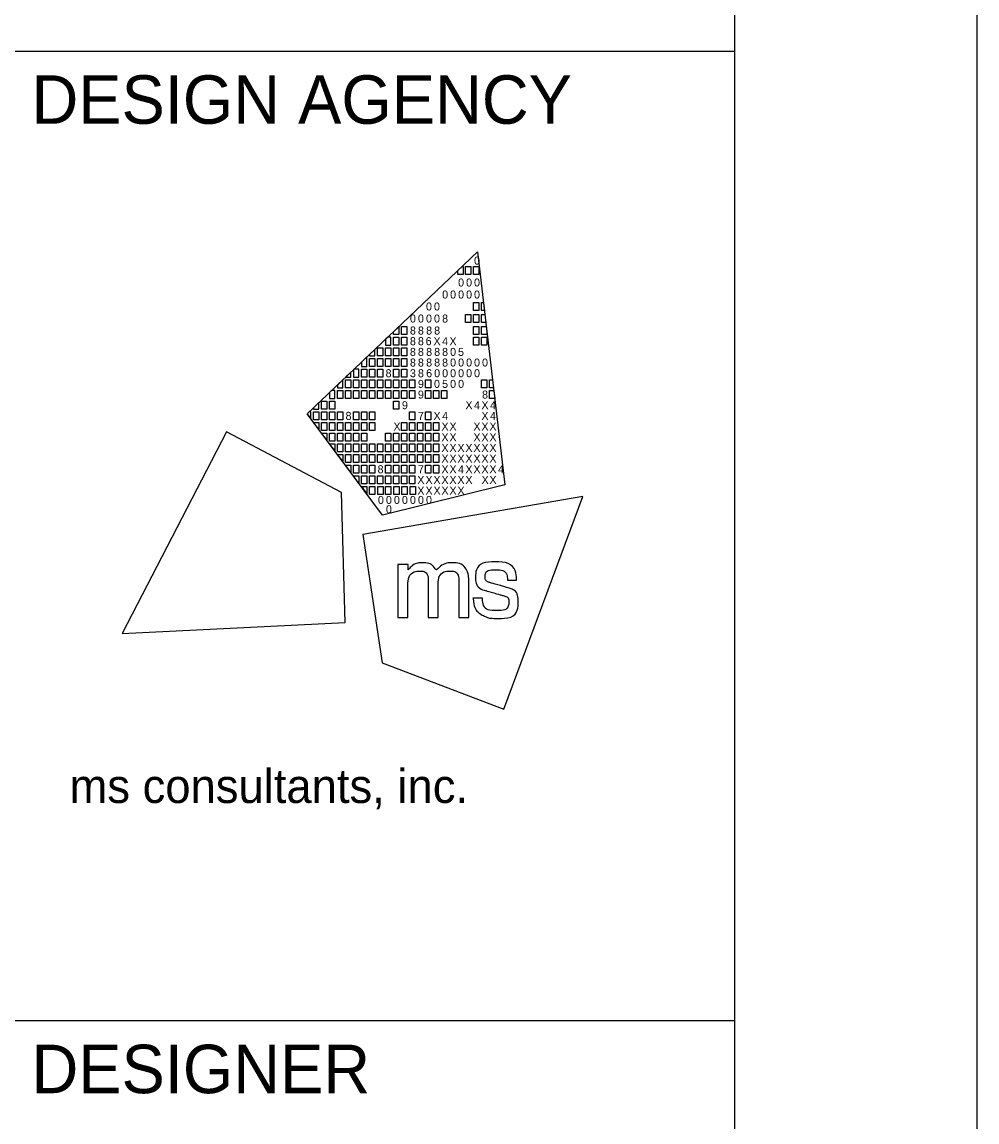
# Model space of a CAD drawing. Extents: x 0.1 to 34.1, y 0.2 to 22.2.
# Drawn here: x 32.139 to 34.108, y 2.456 to 4.725 of the extents above; entities that cross this region are included whole.
import ezdxf

# ---------------------------------------------------------------- set-up
doc = ezdxf.new("R2010")
doc.units = 0
for name, color, linetype in [('Default', 7, 'Continuous'), ('SH_Border', 7, 'Continuous'), ('SH_Cut_Line', 7, 'Continuous'), ('SH_Data', 7, 'Continuous')]:
    doc.layers.add(name, color=color, linetype=linetype)

msp = doc.modelspace()

# ---------------------------------------------------------------- linework, layer by layer
at = {"layer": 'Default'}
for p, q in [((32.7267, 3.9169), (33.0779, 4.2511)), ((33.0779, 4.2511), (33.0779, 4.2511)), ((33.0779, 4.2511), (33.1344, 3.7702)), ((32.8821, 3.708), (32.7267, 3.9169)), ((33.1344, 3.7702), (32.8821, 3.708))]:
    msp.add_line(p, q, dxfattribs=at)
for points in [[(33.0371, 4.2122), (33.046, 4.2208), (33.0481, 4.2208), (33.0481, 4.2043), (33.0371, 4.2043)], [(33.0535, 4.2208), (33.0645, 4.2208), (33.0645, 4.2043), (33.0535, 4.2043)], [(33.07, 4.2208), (33.081, 4.2208), (33.081, 4.2043), (33.07, 4.2043)], [(33.0697, 4.1465), (33.0807, 4.1465), (33.0807, 4.13), (33.0697, 4.13)], [(33.0862, 4.1465), (33.0902, 4.1465), (33.0921, 4.13), (33.0862, 4.13)], [(33.0533, 4.1217), (33.0643, 4.1217), (33.0643, 4.1052), (33.0533, 4.1052)], [(33.0697, 4.1217), (33.0807, 4.1217), (33.0807, 4.1052), (33.0697, 4.1052)], [(33.0862, 4.1217), (33.0931, 4.1217), (33.0951, 4.1052), (33.0862, 4.1052)], [(32.9045, 4.0861), (32.9155, 4.0966), (32.9155, 4.0804), (32.9045, 4.0804)], [(32.9214, 4.0969), (32.9324, 4.0969), (32.9324, 4.0804), (32.9214, 4.0804)], [(33.0697, 4.0969), (33.0807, 4.0969), (33.0807, 4.0804), (33.0697, 4.0804)], [(33.0862, 4.0969), (33.096, 4.0969), (33.0972, 4.0868), (33.0972, 4.0804), (33.0862, 4.0804)], [(32.9049, 4.0749), (32.9159, 4.0749), (32.9159, 4.0584), (32.9049, 4.0584)], [(32.9214, 4.0749), (32.9324, 4.0749), (32.9324, 4.0584), (32.9214, 4.0584)], [(33.0697, 4.0749), (33.0807, 4.0749), (33.0807, 4.0584), (33.0697, 4.0584)], [(33.0862, 4.0749), (33.0972, 4.0749), (33.0972, 4.0584), (33.0862, 4.0584)], [(32.8719, 4.0529), (32.8829, 4.0529), (32.8829, 4.0364), (32.8719, 4.0364)], [(32.8884, 4.0529), (32.8994, 4.0529), (32.8994, 4.0364), (32.8884, 4.0364)], [(32.9049, 4.0529), (32.9159, 4.0529), (32.9159, 4.0364), (32.9049, 4.0364)], [(32.9214, 4.0529), (32.9324, 4.0529), (32.9324, 4.0364), (32.9214, 4.0364)], [(32.8554, 4.0309), (32.8664, 4.0309), (32.8664, 4.0144), (32.8554, 4.0144)], [(32.8719, 4.0309), (32.8829, 4.0309), (32.8829, 4.0144), (32.8719, 4.0144)], [(32.8884, 4.0309), (32.8994, 4.0309), (32.8994, 4.0144), (32.8884, 4.0144)], [(32.9049, 4.0309), (32.9159, 4.0309), (32.9159, 4.0144), (32.9049, 4.0144)], [(32.9214, 4.0309), (32.9324, 4.0309), (32.9324, 4.0144), (32.9214, 4.0144)], [(32.8388, 4.0089), (32.8499, 4.0089), (32.8499, 3.9923), (32.8388, 3.9923)], [(32.8554, 4.0089), (32.8664, 4.0089), (32.8664, 3.9923), (32.8554, 3.9923)], [(32.8719, 4.0089), (32.8829, 4.0089), (32.8829, 3.9923), (32.8719, 3.9923)], [(32.9049, 4.0089), (32.9159, 4.0089), (32.9159, 3.9923), (32.9049, 3.9923)], [(32.9214, 4.0089), (32.9324, 4.0089), (32.9324, 3.9923), (32.9214, 3.9923)], [(32.8058, 3.9868), (32.8168, 3.9868), (32.8168, 3.9703), (32.8058, 3.9703)], [(32.8223, 3.9868), (32.8333, 3.9868), (32.8333, 3.9703), (32.8223, 3.9703)], [(32.8388, 3.9868), (32.8499, 3.9868), (32.8499, 3.9703), (32.8388, 3.9703)], [(32.8554, 3.9868), (32.8664, 3.9868), (32.8664, 3.9703), (32.8554, 3.9703)], [(32.8719, 3.9868), (32.8829, 3.9868), (32.8829, 3.9703), (32.8719, 3.9703)], [(32.8884, 3.9868), (32.8994, 3.9868), (32.8994, 3.9703), (32.8884, 3.9703)], [(32.9049, 3.9868), (32.9159, 3.9868), (32.9159, 3.9703), (32.9049, 3.9703)], [(32.9214, 3.9868), (32.9324, 3.9868), (32.9324, 3.9703), (32.9214, 3.9703)], [(32.9379, 3.9868), (32.9489, 3.9868), (32.9489, 3.9703), (32.9379, 3.9703)], [(32.971, 3.9868), (32.982, 3.9868), (32.982, 3.9703), (32.971, 3.9703)], [(33.0862, 3.9868), (33.0972, 3.9868), (33.0972, 3.9703), (33.0862, 3.9703)], [(33.1027, 3.9868), (33.109, 3.9868), (33.1109, 3.9703), (33.1027, 3.9703)], [(32.7893, 3.9648), (32.8003, 3.9648), (32.8003, 3.9483), (32.7893, 3.9483)], [(32.8058, 3.9648), (32.8168, 3.9648), (32.8168, 3.9483), (32.8058, 3.9483)], [(32.8223, 3.9648), (32.8333, 3.9648), (32.8333, 3.9483), (32.8223, 3.9483)], [(32.8388, 3.9648), (32.8499, 3.9648), (32.8499, 3.9483), (32.8388, 3.9483)], [(32.8554, 3.9648), (32.8664, 3.9648), (32.8664, 3.9483), (32.8554, 3.9483)], [(32.8719, 3.9648), (32.8829, 3.9648), (32.8829, 3.9483), (32.8719, 3.9483)], [(32.8884, 3.9648), (32.8994, 3.9648), (32.8994, 3.9483), (32.8884, 3.9483)], [(32.9049, 3.9648), (32.9159, 3.9648), (32.9159, 3.9483), (32.9049, 3.9483)], [(32.9214, 3.9648), (32.9324, 3.9648), (32.9324, 3.9483), (32.9214, 3.9483)], [(32.9379, 3.9648), (32.9489, 3.9648), (32.9489, 3.9483), (32.9379, 3.9483)], [(32.971, 3.9648), (32.982, 3.9648), (32.982, 3.9483), (32.971, 3.9483)], [(32.9875, 3.9648), (32.9985, 3.9648), (32.9985, 3.9483), (32.9875, 3.9483)], [(33.0038, 3.9648), (33.0149, 3.9648), (33.0149, 3.9483), (33.0038, 3.9483)], [(33.1027, 3.9648), (33.1116, 3.9648), (33.1135, 3.9483), (33.1027, 3.9483)], [(32.7563, 3.9428), (32.7673, 3.9428), (32.7673, 3.9263), (32.7563, 3.9263)], [(32.7728, 3.9428), (32.7838, 3.9428), (32.7838, 3.9263), (32.7728, 3.9263)], [(32.9049, 3.9428), (32.9159, 3.9428), (32.9159, 3.9263), (32.9049, 3.9263)], [(32.7398, 3.9208), (32.7508, 3.9208), (32.7508, 3.9043), (32.7398, 3.9043)], [(32.7563, 3.9208), (32.7673, 3.9208), (32.7673, 3.9043), (32.7563, 3.9043)], [(32.7728, 3.9208), (32.7838, 3.9208), (32.7838, 3.9043), (32.7728, 3.9043)], [(32.7893, 3.9208), (32.8003, 3.9208), (32.8003, 3.9043), (32.7893, 3.9043)], [(32.8223, 3.9208), (32.8333, 3.9208), (32.8333, 3.9043), (32.8223, 3.9043)], [(32.8388, 3.9208), (32.8499, 3.9208), (32.8499, 3.9043), (32.8388, 3.9043)], [(32.8554, 3.9208), (32.8664, 3.9208), (32.8664, 3.9043), (32.8554, 3.9043)], [(32.9379, 3.9208), (32.9489, 3.9208), (32.9489, 3.9043), (32.9379, 3.9043)], [(32.971, 3.9208), (32.982, 3.9208), (32.982, 3.9043), (32.971, 3.9043)], [(32.7398, 3.8988), (32.7508, 3.8988), (32.7508, 3.885)], [(32.7563, 3.8988), (32.7673, 3.8988), (32.7673, 3.8823), (32.7563, 3.8823)], [(32.7728, 3.8988), (32.7838, 3.8988), (32.7838, 3.8823), (32.7728, 3.8823)], [(32.7893, 3.8988), (32.8003, 3.8988), (32.8003, 3.8823), (32.7893, 3.8823)], [(32.8058, 3.8988), (32.8168, 3.8988), (32.8168, 3.8823), (32.8058, 3.8823)], [(32.8223, 3.8988), (32.8333, 3.8988), (32.8333, 3.8823), (32.8223, 3.8823)], [(32.8388, 3.8988), (32.8499, 3.8988), (32.8499, 3.8823), (32.8388, 3.8823)], [(32.8554, 3.8988), (32.8664, 3.8988), (32.8664, 3.8823), (32.8554, 3.8823)], [(32.9214, 3.8988), (32.9324, 3.8988), (32.9324, 3.8823), (32.9214, 3.8823)], [(32.9379, 3.8988), (32.9489, 3.8988), (32.9489, 3.8823), (32.9379, 3.8823)], [(32.9544, 3.8988), (32.9655, 3.8988), (32.9655, 3.8823), (32.9544, 3.8823)], [(32.971, 3.8988), (32.982, 3.8988), (32.982, 3.8823), (32.971, 3.8823)], [(32.9875, 3.8988), (32.9985, 3.8988), (32.9985, 3.8823), (32.9875, 3.8823)], [(32.7563, 3.8767), (32.7673, 3.8767), (32.7673, 3.863)], [(32.7728, 3.8767), (32.7838, 3.8767), (32.7838, 3.8602), (32.7728, 3.8602)], [(32.7893, 3.8767), (32.8003, 3.8767), (32.8003, 3.8602), (32.7893, 3.8602)], [(32.8058, 3.8767), (32.8168, 3.8767), (32.8168, 3.8602), (32.8058, 3.8602)], [(32.8223, 3.8767), (32.8333, 3.8767), (32.8333, 3.8602), (32.8223, 3.8602)], [(32.8388, 3.8767), (32.8499, 3.8767), (32.8499, 3.8602), (32.8388, 3.8602)], [(32.8884, 3.8767), (32.8994, 3.8767), (32.8994, 3.8602), (32.8884, 3.8602)], [(32.9049, 3.8767), (32.9159, 3.8767), (32.9159, 3.8602), (32.9049, 3.8602)], [(32.9214, 3.8767), (32.9324, 3.8767), (32.9324, 3.8602), (32.9214, 3.8602)], [(32.9379, 3.8767), (32.9489, 3.8767), (32.9489, 3.8602), (32.9379, 3.8602)], [(32.9544, 3.8767), (32.9655, 3.8767), (32.9655, 3.8602), (32.9544, 3.8602)], [(32.971, 3.8767), (32.982, 3.8767), (32.982, 3.8602), (32.971, 3.8602)], [(32.9875, 3.8767), (32.9985, 3.8767), (32.9985, 3.8602), (32.9875, 3.8602)], [(32.7728, 3.8547), (32.7838, 3.8547), (32.7838, 3.841)], [(32.7838, 3.8547), (32.7838, 3.8547), (32.7838, 3.8547)], [(32.7893, 3.8547), (32.8003, 3.8547), (32.8003, 3.8382), (32.7893, 3.8382)], [(32.8058, 3.8547), (32.8168, 3.8547), (32.8168, 3.8382), (32.8058, 3.8382)], [(32.8223, 3.8547), (32.8333, 3.8547), (32.8333, 3.8382), (32.8223, 3.8382)], [(32.8388, 3.8547), (32.8499, 3.8547), (32.8499, 3.8382), (32.8388, 3.8382)], [(32.8554, 3.8547), (32.8664, 3.8547), (32.8664, 3.8382), (32.8554, 3.8382)], [(32.8719, 3.8547), (32.8829, 3.8547), (32.8829, 3.8382), (32.8719, 3.8382)], [(32.8884, 3.8547), (32.8994, 3.8547), (32.8994, 3.8382), (32.8884, 3.8382)], [(32.9049, 3.8547), (32.9159, 3.8547), (32.9159, 3.8382), (32.9049, 3.8382)], [(32.9214, 3.8547), (32.9324, 3.8547), (32.9324, 3.8382), (32.9214, 3.8382)], [(32.9379, 3.8547), (32.9489, 3.8547), (32.9489, 3.8382), (32.9379, 3.8382)], [(32.9544, 3.8547), (32.9655, 3.8547), (32.9655, 3.8382), (32.9544, 3.8382)], [(32.971, 3.8547), (32.982, 3.8547), (32.982, 3.8382), (32.971, 3.8382)], [(32.9875, 3.8547), (32.9985, 3.8547), (32.9985, 3.8382), (32.9875, 3.8382)], [(32.7893, 3.8327), (32.8003, 3.8327), (32.8003, 3.8189)], [(32.8058, 3.8327), (32.8168, 3.8327), (32.8168, 3.8162), (32.8058, 3.8162)], [(32.8223, 3.8327), (32.8333, 3.8327), (32.8333, 3.8162), (32.8223, 3.8162)], [(32.8388, 3.8327), (32.8499, 3.8327), (32.8499, 3.8162), (32.8388, 3.8162)], [(32.8554, 3.8327), (32.8664, 3.8327), (32.8664, 3.8162), (32.8554, 3.8162)], [(32.8719, 3.8327), (32.8829, 3.8327), (32.8829, 3.8162), (32.8719, 3.8162)], [(32.8884, 3.8327), (32.8994, 3.8327), (32.8994, 3.8162), (32.8884, 3.8162)], [(32.9049, 3.8327), (32.9159, 3.8327), (32.9159, 3.8162), (32.9049, 3.8162)], [(32.9214, 3.8327), (32.9324, 3.8327), (32.9324, 3.8162), (32.9214, 3.8162)], [(32.9379, 3.8327), (32.9489, 3.8327), (32.9489, 3.8162), (32.9379, 3.8162)], [(32.9544, 3.8327), (32.9655, 3.8327), (32.9655, 3.8162), (32.9544, 3.8162)], [(32.971, 3.8327), (32.982, 3.8327), (32.982, 3.8162), (32.971, 3.8162)], [(32.9875, 3.8327), (32.9985, 3.8327), (32.9985, 3.8162), (32.9875, 3.8162)], [(32.8169, 3.7955), (32.8057, 3.8107), (32.8169, 3.8107)], [(32.8223, 3.8107), (32.8333, 3.8107), (32.8333, 3.7942), (32.8223, 3.7942)], [(32.8388, 3.8107), (32.8499, 3.8107), (32.8499, 3.7942), (32.8388, 3.7942)], [(32.8554, 3.8107), (32.8664, 3.8107), (32.8664, 3.7942), (32.8554, 3.7942)], [(32.8884, 3.8107), (32.8994, 3.8107), (32.8994, 3.7942), (32.8884, 3.7942)], [(32.9049, 3.8107), (32.9159, 3.8107), (32.9159, 3.7942), (32.9049, 3.7942)], [(32.9214, 3.8107), (32.9324, 3.8107), (32.9324, 3.7942), (32.9214, 3.7942)], [(32.9379, 3.8107), (32.9489, 3.8107), (32.9489, 3.7942), (32.9379, 3.7942)], [(32.971, 3.8107), (32.982, 3.8107), (32.982, 3.7942), (32.971, 3.7942)], [(32.9875, 3.8107), (32.9985, 3.8107), (32.9985, 3.7942), (32.9875, 3.7942)], [(32.8331, 3.7732), (32.8223, 3.7887), (32.8333, 3.7887)], [(32.8388, 3.7887), (32.8499, 3.7887), (32.8499, 3.7722), (32.8388, 3.7722)], [(32.8554, 3.7887), (32.8664, 3.7887), (32.8664, 3.7722), (32.8554, 3.7722)], [(32.8719, 3.7887), (32.8829, 3.7887), (32.8829, 3.7722), (32.8719, 3.7722)], [(32.8884, 3.7887), (32.8994, 3.7887), (32.8994, 3.7722), (32.8884, 3.7722)], [(32.9049, 3.7887), (32.9159, 3.7887), (32.9159, 3.7722), (32.9049, 3.7722)], [(32.9214, 3.7887), (32.9324, 3.7887), (32.9324, 3.7722), (32.9214, 3.7722)], [(32.9379, 3.7887), (32.9489, 3.7887), (32.9489, 3.7722), (32.9379, 3.7722)], [(32.8393, 3.7667), (32.8499, 3.7667), (32.8499, 3.7525)], [(32.8554, 3.7667), (32.8664, 3.7667), (32.8664, 3.7502), (32.8554, 3.7502)], [(32.8721, 3.7667), (32.8831, 3.7667), (32.8831, 3.7502), (32.8721, 3.7502)], [(32.8885, 3.7667), (32.8995, 3.7667), (32.8995, 3.7502), (32.8885, 3.7502)], [(32.9052, 3.7667), (32.9162, 3.7667), (32.9162, 3.7502), (32.9052, 3.7502)], [(32.9221, 3.7667), (32.9331, 3.7667), (32.9331, 3.7501), (32.9221, 3.7501)], [(32.9388, 3.7667), (32.9498, 3.7667), (32.9498, 3.7501), (32.9388, 3.7501)]]:
    msp.add_lwpolyline(points, close=True, dxfattribs=at)
for points in [[(32.8994, 4.0749), (32.8927, 4.0749), (32.8884, 4.0708), (32.8884, 4.0584), (32.8994, 4.0584), (32.8994, 4.0749)], [(32.8664, 4.0498), (32.8554, 4.0394), (32.8554, 4.0364), (32.8664, 4.0364), (32.8664, 4.0498)], [(32.8499, 4.0341), (32.8388, 4.0237), (32.8388, 4.0144), (32.8499, 4.0144), (32.8499, 4.0341)], [(32.8168, 4.0027), (32.8059, 3.9923), (32.8168, 3.9923), (32.8168, 4.0027)], [(32.8333, 4.0089), (32.8233, 4.0089), (32.8223, 4.008), (32.8223, 3.9923), (32.8333, 3.9923), (32.8333, 4.0089)], [(32.8003, 3.987), (32.7893, 3.9765), (32.7893, 3.9703), (32.8003, 3.9703), (32.8003, 3.987)], [(32.7838, 3.9648), (32.777, 3.9648), (32.7728, 3.9608), (32.7728, 3.9483), (32.7838, 3.9483), (32.7838, 3.9648)], [(32.7508, 3.9399), (32.7398, 3.9294), (32.7398, 3.9263), (32.7508, 3.9263), (32.7508, 3.9399)], [(32.7343, 3.9208), (32.7307, 3.9208), (32.7267, 3.9169), (32.7343, 3.9067), (32.7343, 3.9208)], [(32.5603, 3.8799), (32.345, 3.4638), (32.8048, 3.4865), (32.7975, 3.7542), (32.5603, 3.8799)], [(33.132, 3.3072), (33.295, 3.7464), (32.8415, 3.6679), (32.8813, 3.4031), (33.132, 3.3072)]]:
    msp.add_lwpolyline(points, dxfattribs=at)
for points in [[(32.9139, 3.4965), (32.9139, 3.4965), (32.9139, 3.6059), (32.9139, 3.6059), (32.9139, 3.6059), (32.9346, 3.6059), (32.9346, 3.6059), (32.9346, 3.6059), (32.9346, 3.5947), (32.9346, 3.5947), (32.9437, 3.6049), (32.9548, 3.6095), (32.9647, 3.6095), (32.978, 3.6095), (32.9883, 3.6022), (32.9928, 3.5916), (33.0006, 3.6031), (33.0142, 3.6096), (33.0257, 3.6096), (33.0417, 3.6096), (33.0542, 3.6), (33.0585, 3.5863), (33.0585, 3.5862), (33.0585, 3.5862), (33.0586, 3.5862), (33.0592, 3.584), (33.0598, 3.5822), (33.0598, 3.5721), (33.0598, 3.5721), (33.0598, 3.4964), (33.0598, 3.4964), (33.0598, 3.4964), (33.0394, 3.4964), (33.0394, 3.4964), (33.0394, 3.4964), (33.0394, 3.5698), (33.0394, 3.5698), (33.0394, 3.5851), (33.031, 3.5924), (33.0202, 3.5924), (33.0086, 3.5924), (32.9971, 3.5821), (32.9971, 3.5651), (32.9971, 3.5651), (32.9971, 3.4965), (32.9971, 3.4965), (32.9971, 3.4965), (32.9765, 3.4965), (32.9765, 3.4965), (32.9765, 3.4965), (32.9765, 3.5709), (32.9765, 3.5709), (32.9765, 3.5853), (32.9679, 3.5924), (32.9588, 3.5924), (32.9475, 3.5924), (32.9345, 3.582), (32.9345, 3.5612), (32.9345, 3.5612), (32.9345, 3.4965), (32.9345, 3.4965), (32.9345, 3.4965), (32.9139, 3.4965), (32.9139, 3.4965)], [(33.0687, 3.5359), (33.0687, 3.5359), (33.0686, 3.5367), (33.0686, 3.5367), (33.0686, 3.5367), (33.0695, 3.5367), (33.0695, 3.5367), (33.0695, 3.5367), (33.0874, 3.5367), (33.0874, 3.5367), (33.0874, 3.5367), (33.0881, 3.5367), (33.0881, 3.5367), (33.0881, 3.5367), (33.0881, 3.536), (33.0881, 3.536), (33.0894, 3.5204), (33.0978, 3.511), (33.1181, 3.511), (33.1364, 3.511), (33.1424, 3.5204), (33.1424, 3.5281), (33.1424, 3.5382), (33.1347, 3.5408), (33.1266, 3.543), (33.1266, 3.543), (33.0961, 3.5517), (33.0961, 3.5517), (33.0812, 3.5559), (33.0739, 3.5669), (33.0739, 3.5792), (33.0739, 3.5953), (33.0859, 3.6112), (33.1143, 3.6112), (33.1439, 3.6112), (33.1581, 3.5935), (33.1581, 3.5745), (33.1581, 3.5745), (33.1581, 3.5737), (33.1581, 3.5737), (33.1581, 3.5737), (33.1573, 3.5737), (33.1573, 3.5737), (33.1573, 3.5737), (33.1403, 3.5737), (33.1403, 3.5737), (33.1403, 3.5737), (33.1397, 3.5737), (33.1397, 3.5737), (33.1397, 3.5737), (33.1396, 3.5744), (33.1396, 3.5744), (33.1393, 3.5858), (33.1318, 3.595), (33.1147, 3.595), (33.0982, 3.595), (33.0934, 3.5868), (33.0934, 3.5807), (33.0934, 3.5758), (33.096, 3.5709), (33.105, 3.5683), (33.105, 3.5683), (33.1346, 3.5598), (33.1346, 3.5598), (33.1554, 3.5539), (33.1618, 3.5427), (33.1618, 3.5289), (33.1618, 3.5112), (33.1501, 3.4948), (33.1178, 3.4948), (33.1043, 3.4948), (33.0968, 3.4971), (33.0914, 3.4998), (33.0782, 3.5064), (33.0701, 3.5186), (33.0687, 3.5359)]]:
    msp.add_open_spline(points, degree=3, dxfattribs=at)
at = {"layer": 'SH_Border'}
for p, q in [((32.1081, 4.6652), (33.6081, 4.6652)), ((32.1081, 2.6652), (33.6081, 2.6652))]:
    msp.add_line(p, q, dxfattribs=at)
msp.add_lwpolyline([(1.6081, 21.6652), (33.6081, 21.6652), (33.6081, 0.6652), (1.6081, 0.6652)], close=True, dxfattribs=at)
at = {"layer": 'SH_Cut_Line'}
msp.add_lwpolyline([(0.1081, 0.1652), (34.1081, 0.1652), (34.1081, 22.1652), (0.1081, 22.1652)], close=True, dxfattribs=at)
at = {"layer": 'SH_Data'}
msp.add_line((32.8581, 3.6652), (32.8581, 3.6652), dxfattribs=at)

# ---------------------------------------------------------------- texts
at = {"layer": 'Default'}
for s, p in [('0', (33.0708, 4.2247)), ('0', (33.0379, 4.1795)), ('0', (33.0544, 4.1795)), ('0', (33.0708, 4.1795)), ('0', (33.005, 4.1547)), ('0', (33.0214, 4.1547)), ('0', (33.0379, 4.1547)), ('0', (33.0544, 4.1547)), ('0', (33.0708, 4.1547)), ('0', (32.9717, 4.13)), ('0', (32.9882, 4.13)), ('0', (32.9386, 4.1052)), ('0', (32.9551, 4.1052)), ('0', (32.9717, 4.1052)), ('0', (32.9882, 4.1052)), ('8', (33.0049, 4.1052)), ('8', (32.9386, 4.0804)), ('8', (32.9551, 4.0804)), ('8', (32.972, 4.0804)), ('8', (32.9885, 4.0804)), ('8', (32.9386, 4.0584)), ('8', (32.9551, 4.0584)), ('6', (32.971, 4.0584)), ('X', (32.9872, 4.0584)), ('4', (33.005, 4.0584)), ('X', (33.0201, 4.0584)), ('8', (32.9386, 4.0363)), ('8', (32.9551, 4.0363)), ('8', (32.972, 4.0363)), ('8', (32.9885, 4.0363)), ('8', (33.0049, 4.0363)), ('0', (33.0214, 4.0363)), ('5', (33.0378, 4.0363)), ('8', (32.9386, 4.0144)), ('8', (32.9551, 4.0144)), ('8', (32.972, 4.0144)), ('8', (32.9885, 4.0144)), ('8', (33.0049, 4.0144)), ('0', (33.0214, 4.0144)), ('0', (33.0379, 4.0144)), ('0', (33.0544, 4.0144)), ('0', (33.0708, 4.0144)), ('0', (33.0873, 4.0144)), ('8', (32.8884, 3.9923)), ('3', (32.9386, 3.9923)), ('8', (32.9551, 3.9923)), ('6', (32.972, 3.9923)), ('0', (32.9885, 3.9923)), ('0', (33.005, 3.9923)), ('0', (33.0214, 3.9923)), ('0', (33.0379, 3.9923)), ('0', (33.0544, 3.9923)), ('0', (33.0708, 3.9923)), ('9', (32.9551, 3.9703)), ('0', (32.9882, 3.9703)), ('5', (33.0049, 3.9703)), ('0', (33.0214, 3.9703)), ('0', (33.0379, 3.9703)), ('9', (32.9551, 3.9483)), ('8', (33.0873, 3.9483)), ('9', (32.9221, 3.9263)), ('X', (33.053, 3.9263)), ('4', (33.0708, 3.9263)), ('X', (33.086, 3.9263)), ('4', (33.1038, 3.9263)), ('8', (32.8058, 3.9043)), ('7', (32.9551, 3.9043)), ('X', (32.9872, 3.9043)), ('4', (33.005, 3.9043)), ('X', (33.086, 3.9043)), ('4', (33.1038, 3.9043)), ('X', (32.9046, 3.8823)), ('X', (33.0036, 3.8823)), ('X', (33.0201, 3.8823)), ('X', (33.0695, 3.8823)), ('X', (33.086, 3.8823)), ('X', (33.1025, 3.8823)), ('X', (33.0036, 3.8602)), ('X', (33.0201, 3.8602)), ('X', (33.0695, 3.8602)), ('X', (33.086, 3.8602)), ('X', (33.1025, 3.8602)), ('X', (33.0036, 3.8382)), ('X', (33.0201, 3.8382)), ('X', (33.0366, 3.8382)), ('X', (33.053, 3.8382)), ('X', (33.0695, 3.8382)), ('X', (33.086, 3.8382)), ('X', (33.1025, 3.8382)), ('X', (33.0036, 3.8162)), ('X', (33.0201, 3.8162)), ('X', (33.0366, 3.8162)), ('X', (33.053, 3.8162)), ('X', (33.0695, 3.8162)), ('X', (33.086, 3.8162)), ('X', (33.1025, 3.8162)), ('8', (32.8719, 3.7942)), ('7', (32.9551, 3.7942)), ('X', (33.0036, 3.7942)), ('X', (33.0201, 3.7942)), ('4', (33.0379, 3.7942)), ('X', (33.053, 3.7942)), ('X', (33.0695, 3.7942)), ('X', (33.086, 3.7942)), ('X', (33.1025, 3.7942)), ('4', (33.1203, 3.7942)), ('X', (32.9538, 3.7722)), ('X', (32.9707, 3.7722)), ('X', (32.9872, 3.7722)), ('X', (33.0036, 3.7722)), ('X', (33.0201, 3.7722)), ('X', (33.0366, 3.7722)), ('X', (33.053, 3.7722)), ('X', (33.0863, 3.7722)), ('X', (33.1025, 3.7722)), ('0', (32.8726, 3.7309)), ('0', (32.8891, 3.7309)), ('0', (32.9056, 3.7309)), ('0', (32.9221, 3.7309)), ('0', (32.9386, 3.7309)), ('X', (32.9538, 3.7501)), ('0', (32.9551, 3.7309)), ('X', (32.9707, 3.7501)), ('0', (32.9717, 3.7309)), ('X', (32.9872, 3.7501)), ('X', (33.0036, 3.7501)), ('X', (33.0201, 3.7501)), ('X', (33.0366, 3.7501)), ('0', (32.8891, 3.7117))]:
    msp.add_text(s, height=0.0165, rotation=360, dxfattribs=at).set_placement(p)
at = {"layer": 'SH_Border'}
msp.add_text('ms consultants, inc.', height=0.07, rotation=360, dxfattribs=at).set_placement((32.2365, 3.1139))
at = {"layer": 'SH_Data'}
for s, p in [('DESIGN AGENCY', (32.1581, 4.5152)), ('DESIGNER', (32.1581, 2.5152))]:
    msp.add_text(s, height=0.1, dxfattribs=at).set_placement(p)

doc.saveas('drawing.dxf')
